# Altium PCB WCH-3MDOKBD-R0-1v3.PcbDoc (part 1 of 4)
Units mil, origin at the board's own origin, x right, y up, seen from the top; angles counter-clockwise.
Board outline 11710.74 x 4477.49 mil, 2 copper layers (Top Layer, Bottom Layer); 233 components, 145 nets, 545 pads, 1448 vias.
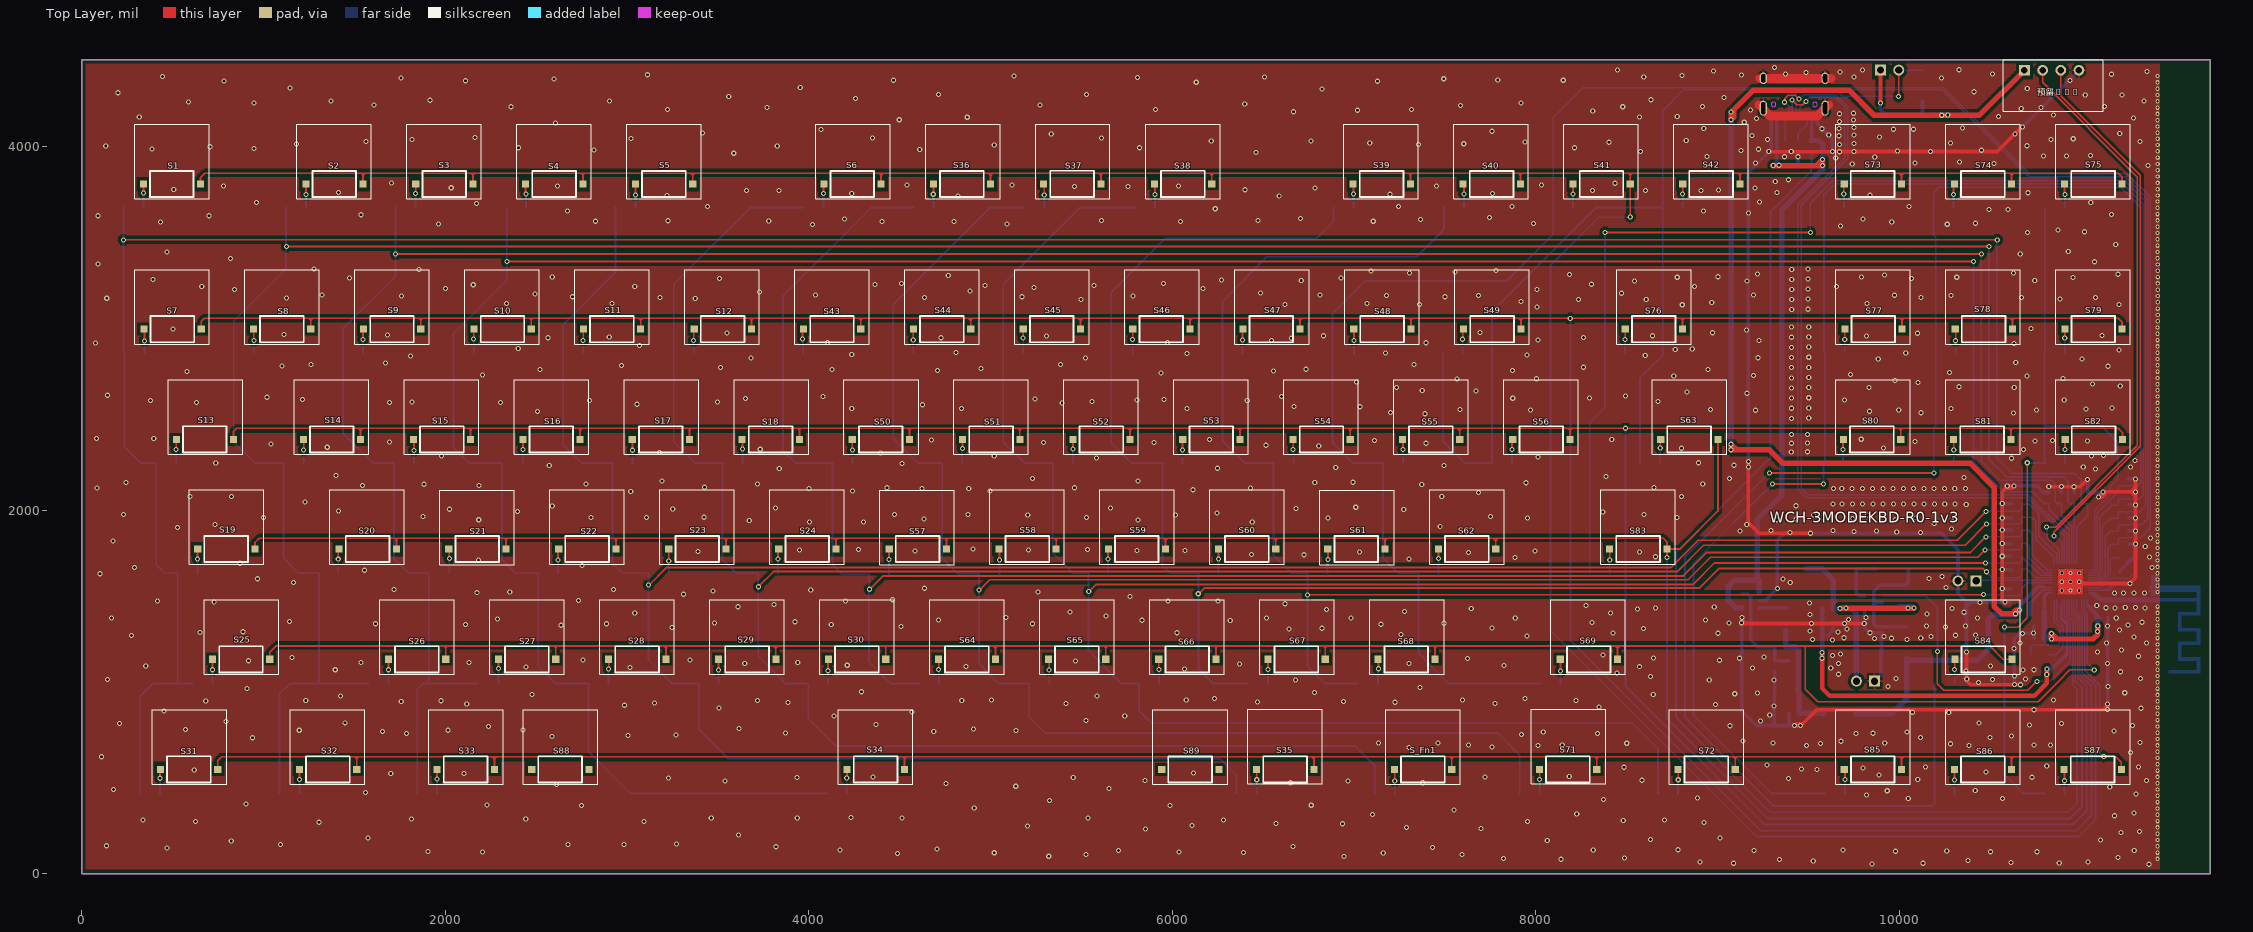
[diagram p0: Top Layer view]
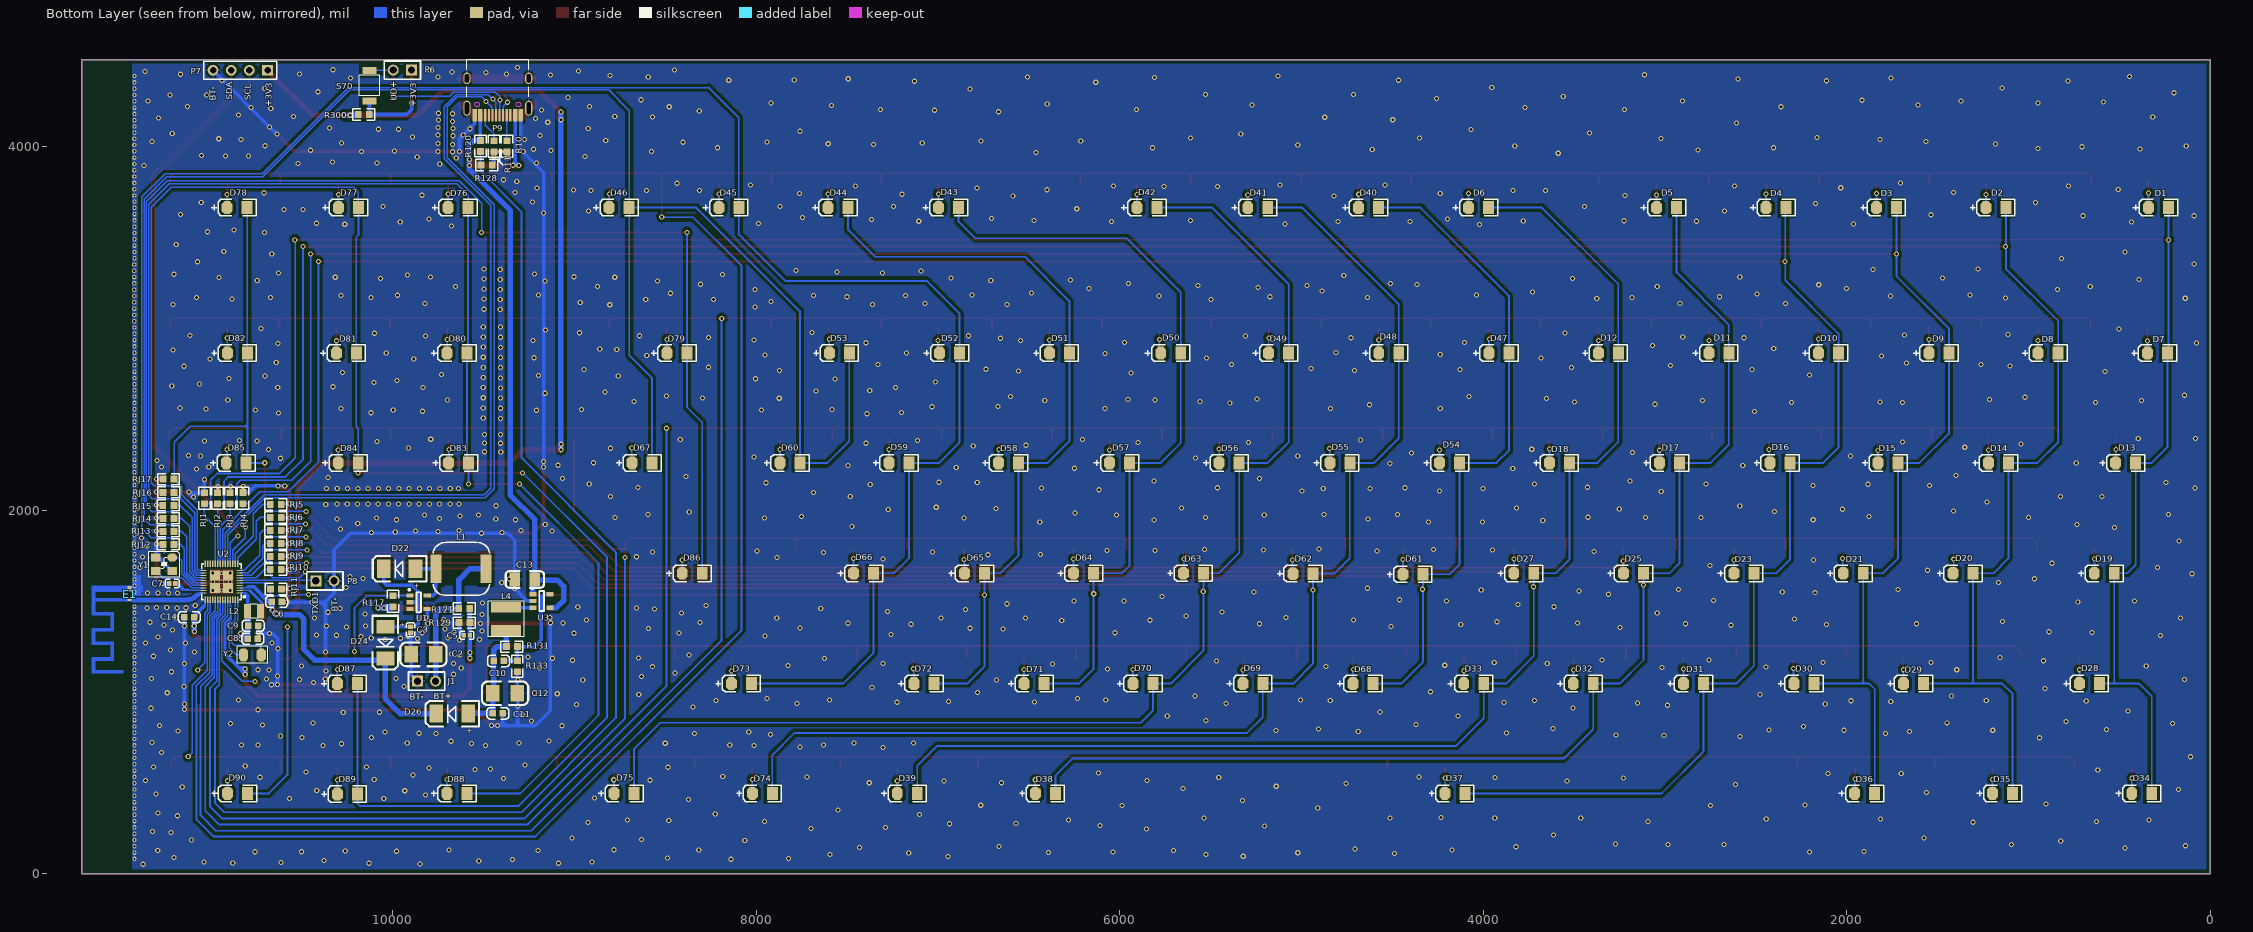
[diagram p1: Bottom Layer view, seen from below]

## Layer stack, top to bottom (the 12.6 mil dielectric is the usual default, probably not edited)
Top Solder: solder mask 0.4, Solder Resist, Dk 3.5
Top Layer: signal copper 1.4
Dielectric1: dielectric 12.6, FR-4, Dk 4.8
Bottom Layer: signal copper 1.4
Bottom Solder: solder mask 0.4, Solder Resist, Dk 3.5

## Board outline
0,0 11710.74,0 11710.74,4477.49 0,4477.49

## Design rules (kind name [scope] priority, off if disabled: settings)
Clearance Clearance_2 [InNamedPolygon('GND1')] p1: gap=6 ignorepadtopadclearanceinfootprint=FALSE
Clearance Clearance_1 [InPolygon] p2: gap=15 ignorepadtopadclearanceinfootprint=FALSE
Clearance [All] p3: gap=6 ignorepadtopadclearanceinfootprint=FALSE
ComponentClearance [All] p1 off: gap=10 collisioncheckmode=3 verticalgap=10 showdistances=FALSE
DiffPairsRouting [All] p1: maxlimit=8 minlimit=6 mostfreqgap=7 toplayer_minwidth=7 toplayer_maxwidth=7 toplayer_prefwidth=7 bottomlayer_minwidth=7 bottomlayer_maxwidth=7 bottomlayer_prefwidth=7 maxuncoupledlength=500
MinimumSolderMaskSliver [All] p1 off: minsoldermaskwidth=10
PolygonConnect PolygonConnect_1 [IsVia] p1: connectstyle=Direct reliefconductorwidth=10 reliefentries=4 polygonreliefangle="90 Angle" airgapwidth=10
PolygonConnect [All] p2: connectstyle=Relief reliefconductorwidth=10 reliefentries=4 polygonreliefangle="90 Angle" airgapwidth=10
RoutingVias [All] p1: holewidth=16 width=28 viastyle="Through Hole" minholewidth=12 minwidth=24 maxholewidth=20 maxwidth=32
SilkToSilkClearance [All] p1 off: silktosilkclearance=10
SilkToSolderMaskClearance SilkscreenOverComponentPads [IsPad] p1 off: minsilkscreentomaskgap=10 clearancetoexposedcopper=TRUE
SolderMaskExpansion [All] p1: expansion=4
Width [All] p1: maxlimit=50 minlimit=6 preferedwidth=10
25 further rules are at their usual default settings.

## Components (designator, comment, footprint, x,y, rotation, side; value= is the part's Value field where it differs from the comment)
C2 "47uF" 3528_C 9898.17,1206.15 r0 bottom
C3 "2.2uF" 0402_C 9901.41,1325.11 r0 bottom
C5 "0.1uF" 0402_C 9607.68,1311.74 r90 bottom
C6 "2.2uF" 0603_C 10610.12,1495.6 r0 bottom
C7 "2.2uF" 0402_C 11228.28,1596.06 r90 bottom
C8 "2.2uF" 0603_C 10741.11,1292.32 r0 bottom
C9 "2.2uF" 0603_C 10739.29,1363.92 r0 bottom
C10 "20pF" 0603_C 9444.56,1170.04 r180 bottom
C11 "0.1uF" 0603_C 9448.12,881.12 r180 bottom
C12 "33uF" 3528_C 9448.23,991.82 r0 bottom
C13 "10uF" 3216_C 9217.66,1618 r180 bottom
C14 "0.1uF" 0603_C 11145.05,1410.61 r180 bottom
D1 "DIODE" 3216+ 340.22,3664.02 r0 bottom locked
D2 "DIODE" 3216+ 1235.34,3664.02 r0 bottom locked
D3 "DIODE" 3216+ 1837.53,3664.02 r0 bottom locked
D4 "DIODE" 3216+ 2444.25,3664.02 r0 bottom locked
D5 "DIODE" 3216+ 3046.47,3664.15 r0 bottom locked
D6 "DIODE" 3216+ 4080.6,3664.02 r0 bottom locked
D7 "DIODE" 3216+ 346.44,2863.47 r0 bottom locked
D8 "DIODE" 3216+ 947.44,2863.47 r0 bottom locked
D9 "DIODE" 3216+ 1547.66,2863.47 r0 bottom locked
D10 "DIODE" 3216+ 2156.27,2863.47 r0 bottom locked
D11 "DIODE" 3216+ 2759.36,2863.47 r0 bottom locked
D12 "DIODE" 3216+ 3367.08,2863.47 r0 bottom locked
D13 "DIODE" 3216+ 521.11,2259.16 r0 bottom locked
D14 "DIODE" 3216+ 1221.16,2259.16 r0 bottom locked
D15 "DIODE" 3216+ 1828.18,2259.16 r0 bottom locked
D16 "DIODE" 3216+ 2422.37,2259.16 r0 bottom locked
D17 "DIODE" 3216+ 3030.91,2259.16 r0 bottom locked
D18 "DIODE" 3216+ 3636.27,2259.16 r0 bottom locked
D19 "DIODE" 3216+ 638.99,1651.91 r0 bottom locked
D20 "DIODE" 3216+ 1416.18,1651.91 r0 bottom locked
D21 "DIODE" 3216+ 2019.59,1651.91 r0 bottom locked
D22 "1N5817" 7227+ 10049.12,1677.06 r180 bottom locked
D23 "DIODE" 3216+ 2621.87,1651.91 r0 bottom locked
D24 "1N5817" 7227+ 10039.49,1183.69 r90 bottom
D25 "DIODE" 3216+ 3228.56,1651.91 r0 bottom locked
D26 "1N5817" 7227+ 9758.84,879.92 r180 bottom
D27 "DIODE" 3216+ 3832.2,1651.91 r0 bottom locked
D28 "DIODE" 3216+ 720.9,1045.22 r0 bottom locked
D29 "DIODE" 3216+ 1688.84,1045.22 r0 bottom locked
D30 "DIODE" 3216+ 2290.6,1045.22 r0 bottom locked
D31 "DIODE" 3216+ 2898.24,1045.22 r0 bottom locked
D32 "DIODE" 3216+ 3505.27,1045.22 r0 bottom locked
D33 "DIODE" 3216+ 4107.43,1045.22 r0 bottom locked
D34 "DIODE" 3216+ 432.75,440.87 r0 bottom locked
D35 "DIODE" 3216+ 1198.31,440.87 r0 bottom locked
D36 "DIODE" 3216+ 1957.05,440.87 r0 bottom locked
D37 "DIODE" 3216+ 4211.36,440.87 r0 bottom locked
D38 "DIODE" 3216+ 6464.02,440.87 r0 bottom locked
D39 "DIODE" 3216+ 7223.58,440.87 r0 bottom locked
D40 "DIODE" 3216+ 4686.32,3664.02 r0 bottom locked
D41 "DIODE" 3216+ 5295.81,3664.02 r0 bottom locked
D42 "DIODE" 3216+ 5905.07,3664.02 r0 bottom locked
D43 "DIODE" 3216+ 6995.94,3664.02 r0 bottom locked
D44 "DIODE" 3216+ 7604.2,3664.02 r0 bottom locked
D45 "DIODE" 3216+ 8205.22,3664.02 r0 bottom locked
D46 "DIODE" 3216+ 8808.27,3664.02 r0 bottom locked
D47 "DIODE" 3216+ 3968.09,2863.47 r0 bottom locked
D48 "DIODE" 3216+ 4574.85,2863.47 r0 bottom locked
D49 "DIODE" 3216+ 5180.47,2863.47 r0 bottom locked
D50 "DIODE" 3216+ 5774.26,2863.47 r0 bottom locked
D51 "DIODE" 3216+ 6386.92,2863.47 r0 bottom locked
D52 "DIODE" 3216+ 6990.5,2863.47 r0 bottom locked
D53 "DIODE" 3216+ 7597.3,2863.47 r0 bottom locked
D54 "DIODE" 3216+ 4239.96,2259.16 r0 bottom locked
D55 "DIODE" 3216+ 4844.14,2259.16 r0 bottom locked
D56 "DIODE" 3216+ 5452.8,2259.16 r0 bottom locked
D57 "DIODE" 3216+ 6055.6,2259.16 r0 bottom locked
D58 "DIODE" 3216+ 6666.44,2259.16 r0 bottom locked
D59 "DIODE" 3216+ 7269.14,2259.16 r0 bottom locked
D60 "DIODE" 3216+ 7869.08,2259.16 r0 bottom locked
D61 "DIODE" 3216+ 4442.3,1646.61 r0 bottom locked
D62 "DIODE" 3216+ 5047.11,1650.08 r0 bottom locked
D63 "DIODE" 3216+ 5649.81,1652.47 r0 bottom locked
D64 "DIODE" 3216+ 6253.38,1652.04 r0 bottom locked
D65 "DIODE" 3216+ 6854.15,1651.91 r0 bottom locked
D66 "DIODE" 3216+ 7463.53,1651.91 r0 bottom locked
D67 "DIODE" 3216+ 8682.18,2259.16 r0 bottom locked
D68 "DIODE" 3216+ 4717.14,1045.22 r0 bottom locked
D69 "DIODE" 3216+ 5322.73,1045.22 r0 bottom locked
D70 "DIODE" 3216+ 5926.55,1045.22 r0 bottom locked
D71 "DIODE" 3216+ 6525.65,1045.22 r0 bottom locked
D72 "DIODE" 3216+ 7131.13,1045.22 r0 bottom locked
D73 "DIODE" 3216+ 8136.22,1045.22 r0 bottom locked
D74 "DIODE" 3216+ 8020.91,440.87 r0 bottom locked
D75 "DIODE" 3216+ 8781.21,440.87 r0 bottom locked
D76 "DIODE" 3216+ 9694.83,3664.02 r0 bottom locked
D77 "DIODE" 3216+ 10297.44,3664.02 r0 bottom locked
D78 "DIODE" 3216+ 10909.68,3664.02 r0 bottom locked
D79 "DIODE" 3216+ 8490.15,2863.47 r0 bottom locked
D80 "DIODE" 3216+ 9700.43,2863.47 r0 bottom locked
D81 "DIODE" 3216+ 10309.39,2863.47 r0 bottom locked
D82 "DIODE" 3216+ 10908.74,2863.47 r0 bottom locked
D83 "DIODE" 3216+ 9691.65,2259.16 r0 bottom locked
D84 "DIODE" 3216+ 10298.64,2259.16 r0 bottom locked
D85 "DIODE" 3216+ 10915.09,2259.16 r0 bottom locked
D86 "DIODE" 3216+ 8406.56,1651.91 r0 bottom locked
D87 "DIODE" 3216+ 10303.89,1045.22 r0 bottom locked
D88 "DIODE" 3216+ 9700.87,440.87 r0 bottom locked
D89 "DIODE" 3216+ 10303.66,437.55 r0 bottom locked
D90 "DIODE" 3216+ 10908.26,441.09 r0 bottom locked
E1 "ANTENNA" ANT-F-1-2.4G-1.6 11446.6,1507.96 r90 bottom
J1 "电源" SIP2-2.54mm 9863.17,1058.77 r270 bottom
L1 "22uH" SMD_7.3x7.8mm 9486.01,1676.23 r270 bottom locked
L2 "22uH" SMD_2x2mm 10762.03,1443.33 r0 bottom
L4 "3.3uH" SMD_5x5mm 9374.78,1464.57 r270 bottom
P6 "Header 2" SIP2-2.54mm 9896.11,4420.24 r90 bottom
P7 "Header 4" HDR1X4 10687.53,4419.13 r0 bottom
P8 "Header 2" SIP2-2.54mm 10421.86,1610.46 r270 bottom
P9 "TYPE-C" TYPE-C-Receptacle-2.0 9421.22,4172.15 r0 bottom locked
R10 "NC(5.1K)" 0603 9370.04,4031.44 r270 bottom
R11 "NC(5.1K)" 0603 9442.13,4032.34 r270 bottom
R117 "1K" 0603 9997.61,1528.94 r270 bottom
R120 "10K" 0603 9515.84,3972.2 r90 bottom
R121 "1M" 0603 9574.94,1458.22 r0 bottom
R128 "10K" 0603 9452.55,3898.85 r0 bottom
R129 "1M" 0603 9634.85,1380.06 r180 bottom
R131 "47K" 0603 9373.45,1248.39 r180 bottom
R133 "10K" 0603 9313.87,1111.26 r90 bottom
R300 "10K" 0603 10128.51,4175.66 r0 bottom
RJ1 "10K" 0603 11034.95,2095.15 r270 bottom
RJ2 "10K" 0603 10963.33,2095.38 r270 bottom
RJ3 "10K" 0603 10893.01,2095.98 r270 bottom
RJ4 "10K" 0603 10822.08,2096.17 r270 bottom
RJ5 "10K" 0603 10611.9,2031.32 r0 bottom
RJ6 "10K" 0603 10611.9,1959.77 r0 bottom
RJ7 "10K" 0603 10611.9,1888.22 r0 bottom
RJ8 "10K" 0603 10611.9,1816.66 r0 bottom
RJ9 "10K" 0603 10611.9,1745.11 r0 bottom
RJ10 "10K" 0603 10611.9,1673.55 r0 bottom
RJ11 "10K" 0603 10610.94,1566.03 r0 bottom
RJ12 "10K" 0603 11263.19,1811.41 r180 bottom
RJ13 "10K" 0603 11263.19,1882.98 r180 bottom
RJ14 "10K" 0603 11263.19,1954.56 r180 bottom
RJ15 "10K" 0603 11263.22,2026.18 r180 bottom
RJ16 "10K" 0603 11262.57,2097.64 r180 bottom
RJ17 "10K" 0603 11262.9,2169.74 r180 bottom
S1 "SW-PB" SMD_6.1x3.65x2.5mm-KEY 654.86,3793.8 r180 top locked
S2 "SW-PB" SMD_6.1x3.65x2.5mm-KEY 1548.73,3793.8 r180 top locked
S3 "SW-PB" SMD_6.1x3.65x2.5mm-KEY 2153.27,3793.8 r180 top locked
S4 "SW-PB" SMD_6.1x3.65x2.5mm-KEY 2757.8,3793.8 r180 top locked
S5 "SW-PB" SMD_6.1x3.65x2.5mm-KEY 3362.34,3793.8 r180 top locked
S6 "SW-PB" SMD_6.1x3.65x2.5mm-KEY 4398.26,3793.97 r180 top locked
S7 "SW-PB" SMD_6.1x3.65x2.5mm-KEY 658.49,2994.96 r180 top locked
S8 "SW-PB" SMD_6.1x3.65x2.5mm-KEY 1260.41,2994.96 r180 top locked
S9 "SW-PB" SMD_6.1x3.65x2.5mm-KEY 1866.19,2994.96 r180 top locked
S10 "SW-PB" SMD_6.1x3.65x2.5mm-KEY 2473.99,2994.96 r180 top locked
S11 "SW-PB" SMD_6.1x3.65x2.5mm-KEY 3075.53,2994.96 r180 top locked
S12 "SW-PB" SMD_6.1x3.65x2.5mm-KEY 3685.01,2994.96 r180 top locked
S13 "SW-PB" SMD_6.1x3.65x2.5mm-KEY 836.42,2388.74 r180 top locked
S14 "SW-PB" SMD_6.1x3.65x2.5mm-KEY 1535.07,2388.74 r180 top locked
S15 "SW-PB" SMD_6.1x3.65x2.5mm-KEY 2140.31,2388.74 r180 top locked
S16 "SW-PB" SMD_6.1x3.65x2.5mm-KEY 2742.63,2388.74 r180 top locked
S17 "SW-PB" SMD_6.1x3.65x2.5mm-KEY 3344.57,2388.74 r180 top locked
S18 "SW-PB" SMD_6.1x3.65x2.5mm-KEY 3948.78,2388.74 r180 top locked
S19 "SW-PB" SMD_6.1x3.65x2.5mm-KEY 953.93,1785.35 r180 top locked
S20 "SW-PB" SMD_6.1x3.65x2.5mm-KEY 1731.56,1785.35 r180 top locked
S21 "SW-PB" SMD_6.1x3.65x2.5mm-KEY 2335.05,1785.35 r180 top locked
S22 "SW-PB" SMD_6.1x3.65x2.5mm-KEY 2939.64,1785.35 r180 top locked
S23 "SW-PB" SMD_6.1x3.65x2.5mm-KEY 3545.39,1785.35 r180 top locked
S24 "SW-PB" SMD_6.1x3.65x2.5mm-KEY 4150.01,1785.35 r180 top locked
S25 "SW-PB" SMD_6.1x3.65x2.5mm-KEY 1035.51,1178.83 r180 top locked
S26 "SW-PB" SMD_6.1x3.65x2.5mm-KEY 2003.11,1178.83 r180 top locked
S27 "SW-PB" SMD_6.1x3.65x2.5mm-KEY 2608.46,1178.83 r180 top locked
S28 "SW-PB" SMD_6.1x3.65x2.5mm-KEY 3214.49,1178.83 r180 top locked
S29 "SW-PB" SMD_6.1x3.65x2.5mm-KEY 3819.1,1178.83 r180 top locked
S30 "SW-PB" SMD_6.1x3.65x2.5mm-KEY 4423.72,1178.83 r180 top locked
S31 "SW-PB" SMD_6.1x3.65x2.5mm-KEY 748.99,573.38 r180 top locked
S32 "SW-PB" SMD_6.1x3.65x2.5mm-KEY 1513.74,573.38 r180 top locked
S33 "SW-PB" SMD_6.1x3.65x2.5mm-KEY 2271.01,573.38 r180 top
S34 "SW-PB" SMD_6.1x3.65x2.5mm-KEY 4526,573.38 r180 top locked
S35 "SW-PB" SMD_6.1x3.65x2.5mm-KEY 6778.66,573.38 r180 top locked
S36 "SW-PB" SMD_6.1x3.65x2.5mm-KEY 5000.82,3793.97 r180 top locked
S37 "SW-PB" SMD_6.1x3.65x2.5mm-KEY 5607.27,3794.25 r180 top locked
S38 "SW-PB" SMD_6.1x3.65x2.5mm-KEY 6216.74,3794.24 r180 top locked
S39 "SW-PB" SMD_6.1x3.65x2.5mm-KEY 7309.83,3793.8 r180 top locked
S40 "SW-PB" SMD_6.1x3.65x2.5mm-KEY 7914.98,3793.8 r180 top locked
S41 "SW-PB" SMD_6.1x3.65x2.5mm-KEY 8519.58,3793.88 r180 top locked
S42 "SW-PB" SMD_6.1x3.65x2.5mm-KEY 9122.54,3793.8 r180 top locked
S43 "SW-PB" SMD_6.1x3.65x2.5mm-KEY 4286.55,2994.96 r180 top locked
S44 "SW-PB" SMD_6.1x3.65x2.5mm-KEY 4890.96,2994.96 r180 top locked
S45 "SW-PB" SMD_6.1x3.65x2.5mm-KEY 5495.41,2994.96 r180 top locked
S46 "SW-PB" SMD_6.1x3.65x2.5mm-KEY 6097.77,2994.96 r180 top locked
S47 "SW-PB" SMD_6.1x3.65x2.5mm-KEY 6703.15,2994.96 r180 top locked
S48 "SW-PB" SMD_6.1x3.65x2.5mm-KEY 7312.97,2994.96 r180 top locked
S49 "SW-PB" SMD_6.1x3.65x2.5mm-KEY 7917.42,2994.96 r180 top locked
S50 "SW-PB" SMD_6.1x3.65x2.5mm-KEY 4554.49,2388.74 r180 top locked
S51 "SW-PB" SMD_6.1x3.65x2.5mm-KEY 5161.33,2388.74 r180 top locked
S52 "SW-PB" SMD_6.1x3.65x2.5mm-KEY 5768.19,2388.74 r180 top locked
S53 "SW-PB" SMD_6.1x3.65x2.5mm-KEY 6372.38,2388.74 r180 top locked
S54 "SW-PB" SMD_6.1x3.65x2.5mm-KEY 6979.24,2388.74 r180 top locked
S55 "SW-PB" SMD_6.1x3.65x2.5mm-KEY 7581.17,2388.74 r180 top locked
S56 "SW-PB" SMD_6.1x3.65x2.5mm-KEY 8188.01,2388.74 r180 top locked
S57 "SW-PB" SMD_6.1x3.65x2.5mm-KEY 4757.72,1785.35 r180 top locked
S58 "SW-PB" SMD_6.1x3.65x2.5mm-KEY 5361.23,1785.35 r180 top locked
S59 "SW-PB" SMD_6.1x3.65x2.5mm-KEY 5963.21,1785.35 r180 top locked
S60 "SW-PB" SMD_6.1x3.65x2.5mm-KEY 6568.85,1785.35 r180 top locked
S61 "SW-PB" SMD_6.1x3.65x2.5mm-KEY 7170.54,1785.35 r180 top locked
S62 "SW-PB" SMD_6.1x3.65x2.5mm-KEY 7778.96,1785.35 r180 top locked
S63 "SW-PB" SMD_6.1x3.65x2.5mm-KEY 9001.52,2388.74 r180 top locked
S64 "SW-PB" SMD_6.1x3.65x2.5mm-KEY 5028.29,1178.83 r180 top locked
S65 "SW-PB" SMD_6.1x3.65x2.5mm-KEY 5634.21,1178.83 r180 top locked
S66 "SW-PB" SMD_6.1x3.65x2.5mm-KEY 6240.4,1178.83 r180 top locked
S67 "SW-PB" SMD_6.1x3.65x2.5mm-KEY 6841.4,1178.83 r180 top locked
S68 "SW-PB" SMD_6.1x3.65x2.5mm-KEY 7445.87,1178.83 r180 top locked
S69 "SW-PB" SMD_6.1x3.65x2.5mm-KEY 8449.06,1178.83 r180 top locked
S70 "Download" 贴片按键 10127.09,4251.02 r90 bottom
S71 "SW-PB" SMD_6.1x3.65x2.5mm-KEY 8335.08,573.38 r180 top locked
S72 "SW-PB" SMD_6.1x3.65x2.5mm-KEY 9096.51,573.38 r180 top locked
S73 "SW-PB" SMD_6.1x3.65x2.5mm-KEY 10011.03,3793.8 r180 top locked
S74 "SW-PB" SMD_6.1x3.65x2.5mm-KEY 10617.3,3793.8 r180 top locked
S75 "SW-PB" SMD_6.1x3.65x2.5mm-KEY 11223.57,3793.8 r180 top locked
S76 "SW-PB" SMD_6.1x3.65x2.5mm-KEY 8806.65,2994.96 r180 top locked
S77 "SW-PB" SMD_6.1x3.65x2.5mm-KEY 10014.84,2994.96 r180 top locked
S78 "SW-PB" SMD_6.1x3.65x2.5mm-KEY 10621.68,2994.96 r180 top locked
S79 "SW-PB" SMD_6.1x3.65x2.5mm-KEY 11224.93,2994.96 r180 top locked
S80 "SW-PB" SMD_6.1x3.65x2.5mm-KEY 10007.05,2388.74 r180 top locked
S81 "SW-PB" SMD_6.1x3.65x2.5mm-KEY 10612.8,2388.74 r180 top locked
S82 "SW-PB" SMD_6.1x3.65x2.5mm-KEY 11226.87,2388.74 r180 top locked
S83 "SW-PB" SMD_6.1x3.65x2.5mm-KEY 8720.81,1785.35 r180 top locked
S84 "SW-PB" SMD_6.1x3.65x2.5mm-KEY 10620.02,1178.83 r180 top locked
S85 "SW-PB" SMD_6.1x3.65x2.5mm-KEY 10011.76,573.38 r180 top locked
S86 "SW-PB" SMD_6.1x3.65x2.5mm-KEY 10617.3,573.38 r180 top locked
S87 "SW-PB" SMD_6.1x3.65x2.5mm-KEY 11220.65,573.38 r180 top locked
S88 "SW-PB" SMD_6.1x3.65x2.5mm-KEY 2791.03,573.38 r180 top (schematic designator S33)
S89 "SW-PB" SMD_6.1x3.65x2.5mm-KEY 6256.56,572.51 r180 top (schematic designator S33)
S_Fn1 "SW-PB" SMD_6.1x3.65x2.5mm-KEY 7536.95,573.38 r180 top locked
U1 "CE8301C33M" SOT-23-5 9904.01,1530.18 r270 bottom
U2 "CH582M" QFN48_5X5 10940.73,1605.7 r90 bottom locked
U3 "CE8502AM" SOT-23-5 9228.25,1537.45 r270 bottom
Y1 "32M" XT3225 11211.35,1738.56 r0 bottom
Y2 "32.768K" FC-135 10820.71,1202.87 r180 bottom

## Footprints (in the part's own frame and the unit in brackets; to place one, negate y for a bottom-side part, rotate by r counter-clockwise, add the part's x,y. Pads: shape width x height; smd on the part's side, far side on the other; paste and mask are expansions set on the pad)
0402_C [mm]
  rect 0.65x0.6 smd mask+0.051: 1(0,0) 2(0,-0.85)
  silkscreen extent -0.58,-1.4 0.57,0.55
0603 [mm]
  rect 0.93x0.98 smd: 1(0,0) 2(1.54,0)
  silkscreen extent -0.76,-0.79 2.3,0.79
0603_C [mil]
  rect 36x36 smd: 1(0,0) 2(55,0)
  silkscreen extent -33,-31 88,31
3216+ [mil]
  oct 60x70 smd: 1(0,0)
  rect 60x70 smd: 2(-110,0)
  silkscreen extent -160,-45 87,45
3216_C [mil]
  rect 60x70 smd: 1(0,0) 2(-110,0)
  silkscreen extent -160,-45 50,45
3528_C [mil]
  rect 75x90 smd: 1(0,0) 2(-135,0)
  silkscreen extent -195,-65 60,65
7227+ [mil]
  rect 75x100 smd: 1(175,0) 2(0,0)
  silkscreen extent -60,-70 235,70
ANT-F-1-2.4G-1.6 [mm]
  rect 0.8x0.6 smd mask+0: 0(1.483,0)
  rect 0.4x0.6 smd mask+0: 1(0,0)
  Top Layer region: 0.24,-0.304 -0.26,-0.304 -0.26,5.027 0.24,5.027
  Top Layer region: 1.94,-0.304 1.04,-0.304 1.04,5.002 1.94,5.002
  Top Layer region: 1.94,4.796 -2.26,4.796 -2.26,5.296 1.94,5.296
  Top Layer region: -1.76,2.157 -2.26,2.157 -2.26,4.977 -1.76,4.977
  Top Layer region: -1.85,2.156 -4.39,2.156 -4.39,2.651 -1.85,2.651
  Top Layer region: -3.96,2.156 -4.46,2.156 -4.46,4.976 -3.96,4.976
  Top Layer region: -3.96,4.796 -6.36,4.796 -6.36,5.296 -3.96,5.296
  Top Layer region: -5.86,2.157 -6.36,2.157 -6.36,4.977 -5.86,4.977
  Top Layer region: -5.875,2.157 -8.364,2.157 -8.364,2.657 -5.875,2.657
  Top Layer region: -8.06,2.157 -8.56,2.157 -8.56,4.977 -8.06,4.977
  Top Layer region: -8.06,4.796 -10.36,4.796 -10.36,5.296 -8.06,5.296
  Top Layer region: -9.86,0.856 -10.36,0.856 -10.36,4.976 -9.86,4.976
FC-135 [mil]
  oct 50x70 smd: 1(0,0) 2(98.43,0)
  silkscreen extent -35,-47 133,47
HDR1X4 [mm] "Connector; Header; 4 Position"
  rect 1.5x1.5 hole 0.9: 1(0,0)
  round 1.5 hole 0.9: 2(2.54,0) 3(5.08,0) 4(7.62,0)
  silkscreen extent -1.27,-1.27 8.89,1.27
QFN48_5X5 [mm]
  round 0.559 hole 0.381 mask+0.102: 0(-1.219,-1.219) 0(-1.219,1.219) 0(0,0) 0(1.219,-1.219) 0(1.219,1.219)
  rect 1.397x1.397 smd mask+0: 0(-0.901,-0.895) 0(-0.901,0.908) 0(0.902,-0.895) 0(0.902,0.908)
  oval 0.18x0.9 smd: 1(-1.575,-2.519) 2(-1.225,-2.519) 3(-0.875,-2.519) 4(-0.525,-2.519) 5(-0.175,-2.519) 6(0.175,-2.519) 7(0.525,-2.519) 8(0.875,-2.519) 9(1.225,-2.519) 10(1.575,-2.519) 25(1.575,2.519) 26(1.225,2.519) 27(0.875,2.519) 28(0.525,2.519) 29(0.175,2.519) 30(-0.175,2.519) 31(-0.525,2.519) 32(-0.875,2.519) 33(-1.225,2.519) 34(-1.575,2.519)
  oval 0.9x0.18 smd: 11(2.514,-2.269) 12(2.514,-1.919) 13(2.514,-1.569) 14(2.514,-1.219) 15(2.514,-0.869) 16(2.514,-0.519) 17(2.514,-0.169) 18(2.514,0.181) 19(2.514,0.531) 20(2.514,0.881) 21(2.514,1.231) 22(2.514,1.581) 23(2.514,1.931) 24(2.514,2.281) 35(-2.514,2.281) 36(-2.514,1.931) 37(-2.514,1.581) 38(-2.514,1.231) 39(-2.514,0.881) 40(-2.514,0.531) 41(-2.514,0.181) 42(-2.514,-0.169) 43(-2.514,-0.519) 44(-2.514,-0.869) 45(-2.514,-1.219) 46(-2.514,-1.569) 47(-2.514,-1.919) 48(-2.514,-2.269)
  silkscreen extent -2.51,-3.31 2.51,2.77
SIP2-2.54mm [mil]
  rect 60x60 hole 40: 1(0,0)
  round 60 hole 40: 2(0,100)
  silkscreen extent -50,-50 50,150
SMD_2x2mm [mm]
  rect 1x2 smd: 1(-0.905,0) 2(0.905,0)
  silkscreen extent -0.47,-1 0.53,1
SMD_5x5mm [mm]
  rect 1.5x4.2 smd: 1(0,0) 2(3.23,0)
  silkscreen extent -0.88,-2.5 4.12,2.5
SMD_6.1x3.65x2.5mm-KEY [mm]
  rect 1x1 smd: 1(0,0) 2(8,0)
  silkscreen extent 0.98,-1.83 7.08,1.83
SMD_7.3x7.8mm [mm]
  rect 4x1.5 smd: 1(0,0) 2(0,-7)
  silkscreen extent -3.69,-7.38 3.69,0.51
SOT-23-5 [mm]
  rect 0.6x1 smd: 1(0,0) 2(0.95,0) 3(1.9,0) 4(1.9,2.4) 5(0,2.4)
  silkscreen extent -0.92,-0.23 2.35,1.54
TYPE-C-Receptacle-2.0 [mm]
  oval 1x1.6 hole 0.6 slot 1.2 at 90 deg: 0(-4.32,-5.15) 0(4.32,-5.15)
  oval 1x2.1 hole 0.6 slot 1.7 at 90 deg: 0(-4.32,-0.97) 0(4.32,-0.97)
  rect 0.6x1.75 smd: A1(-3.225,0) A4(-2.45,0) B1(3.225,0) B4(2.45,0)
  rect 0.3x1.75 smd: A5(-1.25,0) A6(-0.25,0) A7(0.25,0) A8(1.25,0) B5(1.75,0) B6(0.75,0) B7(-0.75,0) B8(-1.75,0)
  Keep-Out Layer circle w0.1: c2.89,-1.5 r0.325
  Keep-Out Layer circle w0.1: c-2.89,-1.5 r0.325
  silkscreen extent -4.32,-7.75 4.32,-2.55
XT3225 [mm]
  oct 1.3x1.1 smd: 1(0,0)
  rect 1.3x1.1 smd: 2(2.3,0) 3(2.3,1.9) 4(0,1.9)
  silkscreen extent -1.02,-0.8 3.27,2.74
贴片按键 [mm]
  rect 1x2 smd: 1(0,0) 3(4.242,0)
  silkscreen extent 0.69,-1.45 3.55,1.45

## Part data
C2 C3 C5 C7: library part C0402
C6 C8 C9 C10 C11 C12 C13 C14: library part CAP, "Capacitor"
D1 D2 D3 D4 D5 D6 D7 D8 D9 D10 D11 D12 D13 D14 D15 D16 D17 D18 D19 D20 D21 D23 D25 D27 D28 D29 D30 D31 D32 D33 D34 D35 D36 D37 D38 D39 D40 D41 D42 D43 D44 D45 D46 D47 D48 D49 D50 D51 D52 D53 D54 D55 D56 D57 D58 D59 D60 D61 D62 D63 D64 D65 D66 D67 D68 D69 D70 D71 D72 D73 D74 D75 D76 D77 D78 D79 D80 D81 D82 D83 D84 D85 D86 D87 D88 D89 D90: "Diode"
D22 D24 D26: library part "D Schottky", "Schottky Diode"
E1: "Generic Antenna"
J1: library part HDR1x2, "Connector"
L1: library part 1.05.0226.04, Value2=¶î¶¨µ, Value3=˳?
L2: library part INDUCTANCE, "Inductance"
L4: library part INDUCTOR
P6 P8: "Header, 2-Pin"
P7: "Header, 4-Pin"
P9: library part TYPE-C1
R10 R11 RJ1 RJ2 RJ3 RJ4 RJ5 RJ6 RJ7 RJ8 RJ9 RJ10 RJ11 RJ12 RJ13 RJ14 RJ15 RJ16 RJ17: library part Res2, "Resistor"
R117 R120 R121 R128 R129: library part RES, "Resistor"
R131 R133: library part R
R300: library part DZ
S70: library part SW-PB, "Switch"
U1: library part 1.07.0021.05
U2: "RISC-V MCU with BLE/2*USB/ADC/PWM/SPI/I2C/4*UART"
U3: library part FP6160
Y1 Y2: library part XTAL, "Crystal Oscillator"

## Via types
v1: diameter 28, hole 16, Top Layer to Bottom Layer, tented both sides, 1320 vias
v2: diameter 24, hole 12, Top Layer to Bottom Layer, tented both sides, 128 vias

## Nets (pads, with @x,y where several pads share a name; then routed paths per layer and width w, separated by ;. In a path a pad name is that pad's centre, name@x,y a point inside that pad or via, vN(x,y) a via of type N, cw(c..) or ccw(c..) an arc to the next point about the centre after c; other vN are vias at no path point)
+3V3: C6.2 D24.2 D26.2 P7.1 R300.2 U2.3 | length 8404.6
  Top Layer w30: v1@9073.6,4146.86 v1@9073.6,4158.49 ; v1(9073.74,4146.86) 9088.24,4161.35 9088.24,4173.14 ; v1(10232.93,4171.94) 10440.34,4171.94 P7.1@10687.53,4419.13 ; v1@10265.81,4170.5 9861.43,4170.5 9722.65,4309.28 9198.01,4309.28 9088.24,4199.51 ; v1(10659.82,1449.55) v1@10659.15,1449.55 ; v1@9073.6,4158.49 9073.6,4184.87 9088.24,4199.51 ; v1@9073.6,4158.49 9088.24,4173.14 ; 9088.24,4173.14 9088.24,4199.51 ; 9102.65,2332.52 v1(9073.47,2361.7) 9073.47,2332.64 9073.6,2332.52 9102.65,2332.52 ; 9102.65,2332.52 9282.41,2332.52 9356.73,2258.21 10388.69,2258.21 10521.51,2125.39 10521.51,1470.41 10562.17,1429.75 10621.68,1429.75 ; 10621.68,1429.75 v1(10639.36,1429.75) v1@10659.15,1449.55 ; 10621.68,1429.75 10641.47,1449.55 v1@10659.15,1449.55
  Bottom Layer w7: 10665.12,1472.32 10668.02,1472.32 C6.2@10682.8,1487.11 ; U2.3@10841.57,1571.27 10805.13,1571.27 ; C6.2@10673.61,1487.11 C6.2@10682.1,1495.6 ; C6.2@10673.61,1487.11 C6.2@10682.8,1487.11 ; C6.2@10673.61,1487.11 C6.2@10665.12,1495.6 C6.2@10673.69,1495.6 ; C6.2@10673.69,1495.6 C6.2@10682.1,1495.6 ; C6.2@10673.69,1495.6 10761.64,1583.55 10792.85,1583.55 10799.18,1577.22 ; C6.2@10682.1,1495.6 C6.2@10682.77,1495.6 ; C6.2@10682.77,1495.6 10691.29,1495.6 ; C6.2@10682.77,1495.6 10764.39,1577.22 10772.91,1577.22 ; C6.2@10682.8,1487.11 10691.29,1495.6 ; 10691.29,1495.6 10766.96,1571.27 ; 10766.96,1571.27 10805.13,1571.27 ; 10766.96,1571.27 10772.91,1577.22 ; 10772.91,1577.22 10799.18,1577.22 ; 10799.18,1577.22 10805.13,1571.27
  Bottom Layer w30: v1@9073.6,4188.5 v1(9073.74,4146.86) 9073.74,2361.7 v1@9073.74,2337.08 ; D26.2@9758.84,879.92 9958.55,879.92 10039.49,960.86 D24.2@10039.49,1183.69 10048.53,1174.65 10429.25,1174.65 10487.53,1232.93 10487.53,1399.45 10512.17,1424.1 v1@10638.03,1424.1 ; R300.2@10189.14,4175.66 10192.61,4172.19 v1(10265.81,4172.19) ; v1@10638.08,1424.05 10665.12,1451.09 10665.12,1472.32 C6.2@10665.12,1495.6
  other v1: 9073.47,2331.61 9073.24,4188.5
+5V: C13.1 P9.A4 P9.B4 R120.2 U3.1 U3.4 | length 3861.9
  Top Layer w30: v1(9305.76,3895.85) 9306.64,3894.97 9543.82,3894.97 ; v1(9577.53,3894.97) 9543.82,3894.97 ; v1@9577.53,3897.37 9576.14,3898.75 v1(9576.14,3927.29) 9543.82,3894.97
  Bottom Layer w20: P9.A4@9324.77,4172.15 9324.77,3914.85 ; R120.2@9515.84,4032.83 9517.68,4034.67 P9.B4@9517.68,4172.15 ; 9324.77,3914.85 v1(9305.76,3895.85) 9335.62,3895.85 v1(9336.41,3896.64) 9336.41,3903.2 9324.77,3914.85
  Bottom Layer w30: U3.4@9133.76,1462.65 9098.18,1462.65 9059.03,1501.79 9059.03,1580.58 9092.99,1614.55 9226.88,1614.55 9228.25,1613.18 U3.1@9228.25,1544.25 ; C13.1@9217.66,1618 9217.66,1946.65 9352.33,2081.31 9352.33,3646.95 9577.53,3872.15 v1(9577.53,3894.97) 9577.53,4011.01 9555.71,4032.83 R120.2@9515.84,4032.83
BT+: C2.2 J1.2 L1.1 R117.2 R121.2 | length 1422.9
  Top Layer w30: v1(9674.11,1459.15) 9675.44,1460.48 v1(9706.68,1460.48) v1(10079.14,1460.48)
  Bottom Layer w30: L1.1@9486.01,1676.23 9575.78,1676.23 9635.57,1616.44 R121.2@9635.57,1458.22 9736.37,1458.22 9763.17,1431.43 C2.2@9763.17,1206.15 J1.2@9763.17,1058.77 J1.2@9760.39,1055.99 ; R117.2@9997.61,1468.31 10071.31,1468.31 v1(10079.14,1460.48) 10005.45,1460.48 R117.2@9997.61,1468.31
  other v1: 10047.81,1460.77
